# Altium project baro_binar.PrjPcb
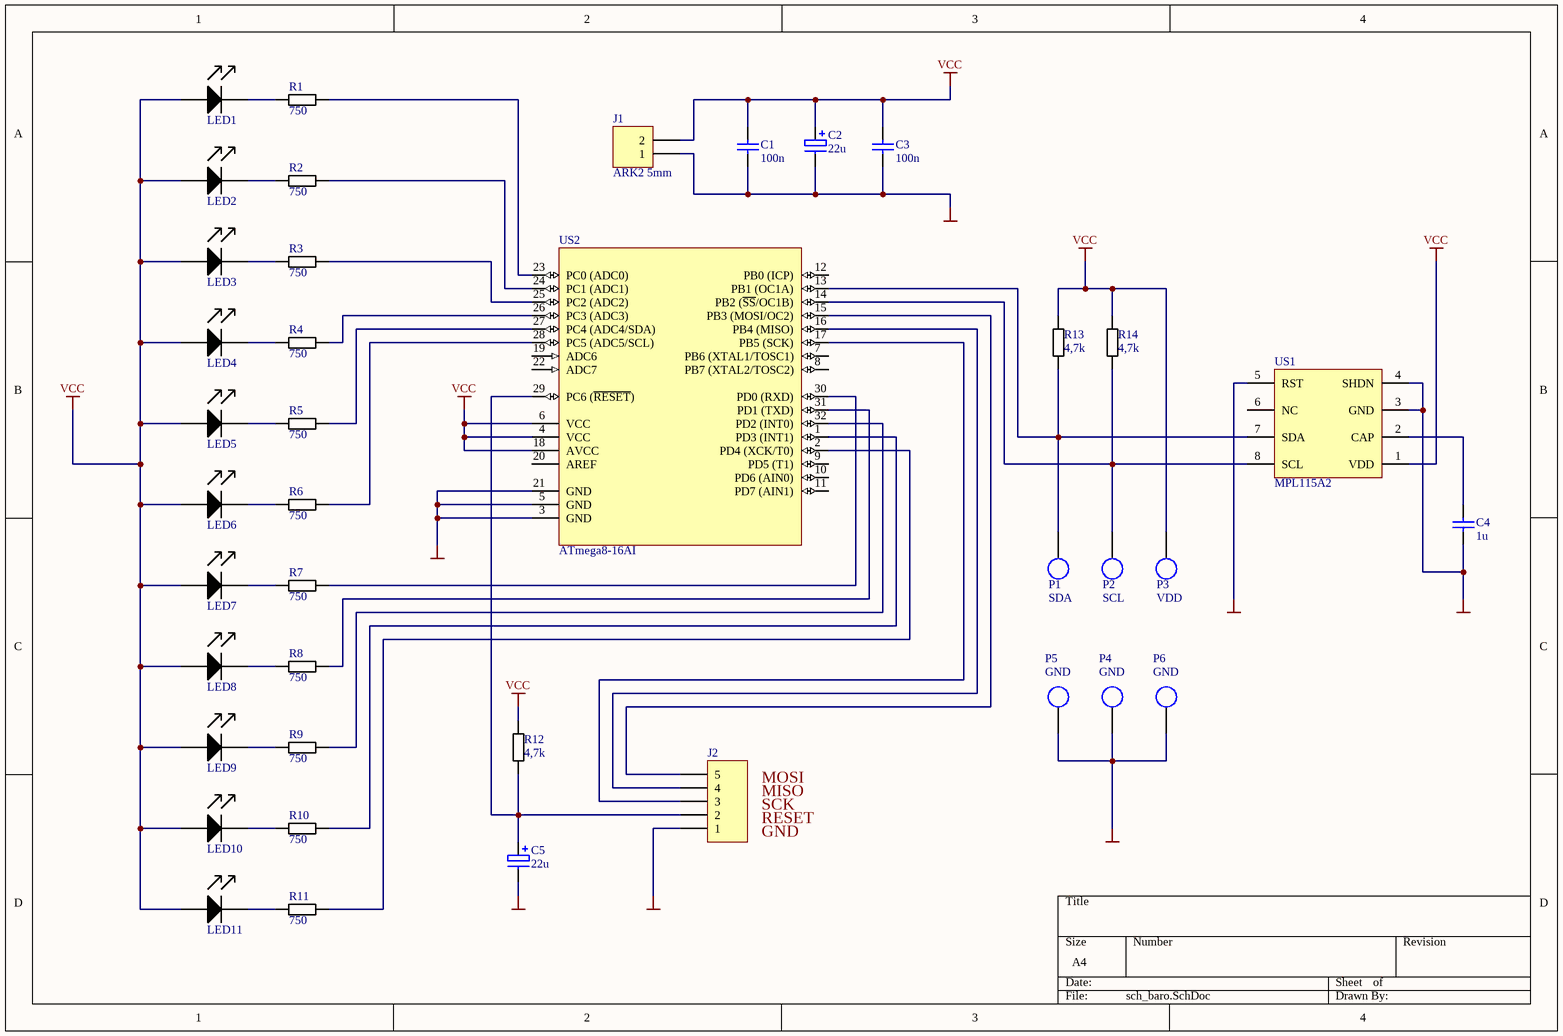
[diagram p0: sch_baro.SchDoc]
1 sheet, 40 parts. Net scope: global (net labels, ports and power ports of the same name join across sheets).
Board file: pcb_baro.PcbDoc

## Sheet sch_baro.SchDoc
size A4

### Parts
C1  100n  [MELF-1206]
C2  22u  [Tantal B 3528-1411]
C3  100n  [MELF-1206]
C4  1u  [MELF-1206]
C5  22u  [Tantal B 3528-1411]
J1  ARK2 5mm  [ARK2 5mm]
J2  Header 5H  [HDR1X5H]  (value not drawn)
LED1  LED  [LED 5mm]  (value not drawn)
LED2  LED  [LED 5mm]  (value not drawn)
LED3  LED  [LED 5mm]  (value not drawn)
LED4  LED  [LED 5mm]  (value not drawn)
LED5  LED  [LED 5mm]  (value not drawn)
LED6  LED  [LED 5mm]  (value not drawn)
LED7  LED  [LED 5mm]  (value not drawn)
LED8  LED  [LED 5mm]  (value not drawn)
LED9  LED  [LED 5mm]  (value not drawn)
LED10  LED  [LED 5mm]  (value not drawn)
LED11  LED  [LED 5mm]  (value not drawn)
P1  SDA  [Pad SMD 2x4mm]
P2  SCL  [Pad SMD 2x4mm]
P3  VDD  [Pad SMD 2x4mm]
P4  GND  [Pad SMD 2x4mm]
P5  GND  [Pad SMD 2x4mm]
P6  GND  [Pad SMD 2x4mm]
R1  750  [MELF-1206]
R2  750  [MELF-1206]
R3  750  [MELF-1206]
R4  750  [MELF-1206]
R5  750  [MELF-1206]
R6  750  [MELF-1206]
R7  750  [MELF-1206]
R8  750  [MELF-1206]
R9  750  [MELF-1206]
R10  750  [MELF-1206]
R11  750  [MELF-1206]
R12  4,7k  [MELF-1206]
R13  4,7k  [MELF-1206]
R14  4,7k  [MELF-1206]
US1  MPL115A2  [MPL115A2]
US2  ATmega8-16AI  [32A_N]

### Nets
GND: C1.2 C2.2 C3.2 C4.2 C5.2 J1.1 J2.1 P4.1 P5.1 P6.1 US1.3(GND) US1.4(SHDN) US1.5(RST) US2.3(GND) US2.5(GND) US2.21(GND)
VCC: C1.1 C2.1 C3.1 J1.2 LED1.A LED2.A LED3.A LED4.A LED5.A LED6.A LED7.A LED8.A LED9.A LED10.A LED11.A P3.1 R12.1 R13.1 R14.1 US1.1(VDD) US2.4(VCC) US2.6(VCC) US2.18(AVCC)
NetC4_1: C4.1 US1.2(CAP)
NetC5_1: C5.1 J2.2 R12.2 US2.29(PC6_(~{RESET}))
NetJ2_3: J2.3 US2.17(PB5_(SCK))
NetJ2_4: J2.4 US2.16(PB4_(MISO))
NetJ2_5: J2.5 US2.15(PB3_(MOSI/OC2))
NetLED1_K: LED1.K R1.2
NetLED2_K: LED2.K R2.2
NetLED3_K: LED3.K R3.2
NetLED4_K: LED4.K R4.2
NetLED5_K: LED5.K R5.2
NetLED6_K: LED6.K R6.2
NetLED7_K: LED7.K R7.2
NetLED8_K: LED8.K R8.2
NetLED9_K: LED9.K R9.2
NetLED10_K: LED10.K R10.2
NetLED11_K: LED11.K R11.2
NetP1_1: P1.1 R13.2 US1.7(SDA) US2.13(PB1_(OC1A))
NetP2_1: P2.1 R14.2 US1.8(SCL) US2.14(PB2_(~{SS}/OC1B))
NetR1_1: R1.1 US2.23(PC0_(ADC0))
NetR2_1: R2.1 US2.24(PC1_(ADC1))
NetR3_1: R3.1 US2.25(PC2_(ADC2))
NetR4_1: R4.1 US2.26(PC3_(ADC3))
NetR5_1: R5.1 US2.27(PC4_(ADC4/SDA))
NetR6_1: R6.1 US2.28(PC5_(ADC5/SCL))
NetR7_1: R7.1 US2.30(PD0_(RXD))
NetR8_1: R8.1 US2.31(PD1_(TXD))
NetR9_1: R9.1 US2.32(PD2_(INT0))
NetR10_1: R10.1 US2.1(PD3_(INT1))
NetR11_1: R11.1 US2.2(PD4_(XCK/T0))

Not connected (* = marked no-connect by the designer): US1 6(NC); US2 7(PB6_(XTAL1/TOSC1)) 8(PB7_(XTAL2/TOSC2)) 9(PD5_(T1)) 10(PD6_(AIN0)) 11(PD7_(AIN1)) 12(PB0_(ICP)) 19(ADC6) 20(AREF) 22(ADC7)

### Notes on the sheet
- MOSI
- GND
- RESET
- SCK
- MISO

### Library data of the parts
C1 C3 C4 = kondensator
C2 C5 = kond biegunowy: Polarized Capacitor
J1 = ARK2
J2 = Header 5H: Header, 5-Pin, Right Angle
P1-P6 = Pad
R1-R14 = rezystor
US2 = ATmega8-16AI: 8-Bit AVR Microcontroller with 8K Bytes of In-System Programmable Flash Memory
